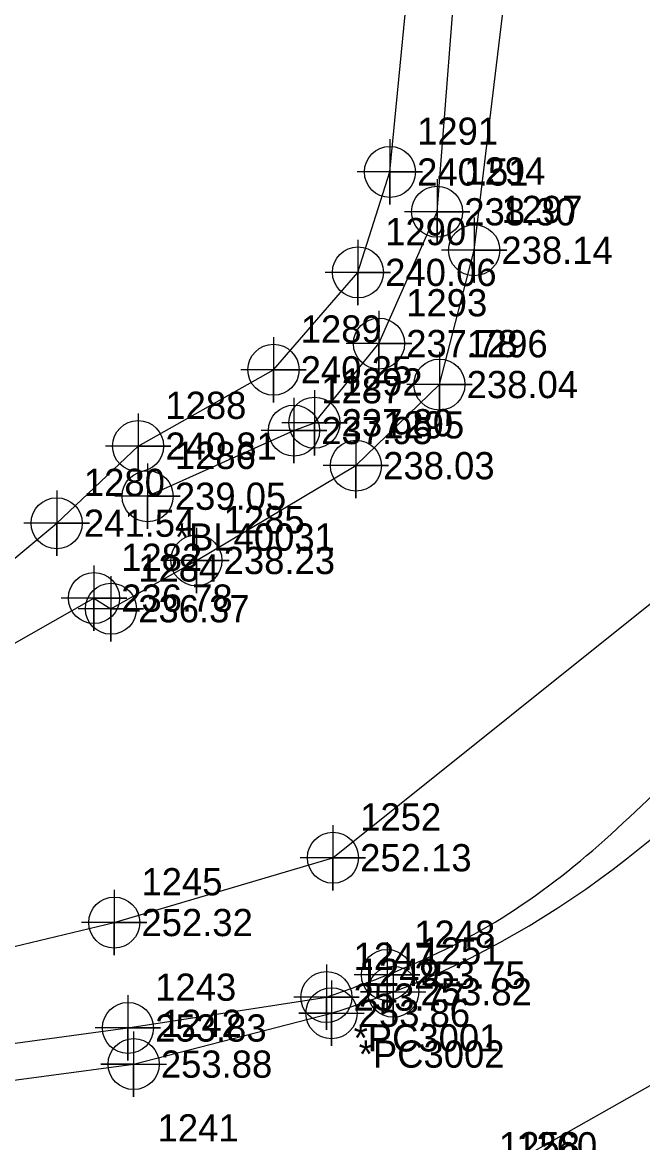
# Model space of a CAD drawing. Extents: x 2130962 to 2131465, y 643052 to 644206.
# Drawn here: x 2131138.3 to 2131195.3, y 643203.3 to 643306.2 of the extents above; entities that cross this region are included whole.
import ezdxf

# ---------------------------------------------------------------- set-up
doc = ezdxf.new("R2010")
doc.units = 0
for name, color, linetype in [('Exist DTM Breakline', 7, 'Continuous'), ('Exist DTM Breakline Cogo Elevation', 7, 'Continuous'), ('Exist DTM Breakline Cogo Number', 7, 'Continuous'), ('Exist DTM Breakline Cogo Point CELL', 7, 'Continuous'), ('Exist DTM Drainline', 7, 'Continuous'), ('Exist DTM Drainline Cogo Comment', 7, 'Continuous'), ('Exist DTM Drainline Cogo Elevation', 7, 'Continuous'), ('Exist DTM Drainline Cogo Number', 7, 'Continuous'), ('Exist DTM Drainline Cogo Point CELL', 7, 'Continuous'), ('Exist Roads EOP', 7, 'Continuous'), ('Exist Roads EOP Cogo Comment', 7, 'Continuous'), ('Exist Roads EOP Cogo Elevation', 7, 'Continuous'), ('Exist Roads EOP Cogo Number', 7, 'Continuous'), ('Exist Roads EOP Cogo Point CELL', 7, 'Continuous'), ('Exist Roads EOT', 7, 'Continuous'), ('Exist Roads EOT Cogo Comment', 7, 'Continuous'), ('Exist Roads EOT Cogo Elevation', 7, 'Continuous'), ('Exist Roads EOT Cogo Number', 7, 'Continuous'), ('Exist Roads EOT Cogo Point CELL', 7, 'Continuous')]:
    doc.layers.add(name, color=color, linetype=linetype)

msp = doc.modelspace()

# ---------------------------------------------------------------- linework, layer by layer
at = {"layer": 'Exist DTM Breakline'}
for points in [[(2131000.7408, 643235.0731), (2131050.2503, 643235.0771), (2131099.3971, 643233.3967), (2131102.4734, 643233.467), (2131117.9784, 643240.6457), (2131141.4902, 643260.2289), (2131148.9668, 643267.309), (2131161.3925, 643274.3195), (2131169.1458, 643283.2692), (2131172.0772, 643292.493), (2131174.434, 643316.7319), (2131174.0607, 643347.0813), (2131174.2633, 643367.3367), (2131180.4607, 643413.966), (2131183.0424, 643464.7744), (2131179.7562, 643510.5479), (2131157.5016, 643561.2065), (2131139.0887, 643604.6918), (2131124.996, 643650.6897)], [(2131000.2707, 643222.2884), (2131049.3172, 643219.2511), (2131099.5024, 643216.1866), (2131123.0232, 643217.8518), (2131146.7721, 643223.5416), (2131166.8509, 643229.4959), (2131199.4918, 643255.6512), (2131208.4065, 643272.9132), (2131217.3052, 643317.6851), (2131214.0619, 643367.4973), (2131211.0353, 643416.1836)]]:
    msp.add_lwpolyline(points, dxfattribs=at)
at = {"layer": 'Exist DTM Breakline Cogo Point CELL'}
for points in [[(2131172.0772, 643295.493), (2131172.0772, 643289.493), (2131172.0772, 643292.493), (2131175.0772, 643292.493), (2131169.0772, 643292.493)], [(2131169.1458, 643286.2692), (2131169.1458, 643280.2692), (2131169.1458, 643283.2692), (2131172.1458, 643283.2692), (2131166.1458, 643283.2692)], [(2131161.3925, 643277.3195), (2131161.3925, 643271.3195), (2131161.3925, 643274.3195), (2131164.3925, 643274.3195), (2131158.3925, 643274.3195)], [(2131148.9668, 643270.309), (2131148.9668, 643264.309), (2131148.9668, 643267.309), (2131151.9668, 643267.309), (2131145.9668, 643267.309)], [(2131141.4902, 643263.2289), (2131141.4902, 643257.2289), (2131141.4902, 643260.2289), (2131144.4902, 643260.2289), (2131138.4902, 643260.2289)], [(2131166.8509, 643232.4959), (2131166.8509, 643226.4959), (2131166.8509, 643229.4959), (2131169.8509, 643229.4959), (2131163.8509, 643229.4959)], [(2131146.7721, 643226.5416), (2131146.7721, 643220.5416), (2131146.7721, 643223.5416), (2131149.7721, 643223.5416), (2131143.7721, 643223.5416)]]:
    msp.add_lwpolyline(points, dxfattribs=at)
for centre in [(2131172.0772, 643292.493), (2131169.1458, 643283.2692), (2131161.3925, 643274.3195), (2131148.9668, 643267.309), (2131141.4902, 643260.2289), (2131166.8509, 643229.4959), (2131146.7721, 643223.5416)]:
    msp.add_circle(centre, 2.344, dxfattribs=at)
at = {"layer": 'Exist DTM Drainline'}
for points in [[(2131000.2029, 643226.7228), (2131050.9884, 643228.9032), (2131099.0297, 643228.5605), (2131120.2968, 643239.3591), (2131144.9156, 643253.3469), (2131146.4739, 643252.3674), (2131154.3188, 643256.8046), (2131168.9618, 643265.5132), (2131176.6257, 643272.964), (2131179.8144, 643285.303), (2131183.3842, 643315.022), (2131190.1471, 643365.8731), (2131190.1489, 643413.686), (2131192.3886, 643466.4632), (2131188.8083, 643512.615), (2131184.0059, 643563.7066), (2131175.3, 643610.7482), (2131168.3784, 643658.7431), (2131156.7476, 643707.4708), (2131144.9036, 643754.0458), (2131132.9438, 643802.544), (2131118.0831, 643847.9475), (2131104.0084, 643896.8663), (2131096.3866, 643919.4077)], [(2131149.8388, 643262.7067), (2131163.2746, 643268.7404), (2131165.1512, 643269.4553), (2131171.0778, 643276.7299), (2131176.4073, 643288.8357), (2131178.5355, 643315.9841), (2131178.9558, 643366.5567), (2131185.1892, 643414.0962), (2131192.3516, 643466.0067)]]:
    msp.add_lwpolyline(points, dxfattribs=at)
at = {"layer": 'Exist DTM Drainline Cogo Point CELL'}
for points in [[(2131176.4073, 643291.8357), (2131176.4073, 643285.8357), (2131176.4073, 643288.8357), (2131179.4073, 643288.8357), (2131173.4073, 643288.8357)], [(2131179.8144, 643288.303), (2131179.8144, 643282.303), (2131179.8144, 643285.303), (2131182.8144, 643285.303), (2131176.8144, 643285.303)], [(2131171.0778, 643279.7299), (2131171.0778, 643273.7299), (2131171.0778, 643276.7299), (2131174.0778, 643276.7299), (2131168.0778, 643276.7299)], [(2131176.6257, 643275.964), (2131176.6257, 643269.964), (2131176.6257, 643272.964), (2131179.6257, 643272.964), (2131173.6257, 643272.964)], [(2131165.1512, 643272.4553), (2131165.1512, 643266.4553), (2131165.1512, 643269.4553), (2131168.1512, 643269.4553), (2131162.1512, 643269.4553)], [(2131163.2746, 643271.7404), (2131163.2746, 643265.7404), (2131163.2746, 643268.7404), (2131166.2746, 643268.7404), (2131160.2746, 643268.7404)], [(2131168.9618, 643268.5132), (2131168.9618, 643262.5132), (2131168.9618, 643265.5132), (2131171.9618, 643265.5132), (2131165.9618, 643265.5132)], [(2131149.8388, 643265.7067), (2131149.8388, 643259.7067), (2131149.8388, 643262.7067), (2131152.8388, 643262.7067), (2131146.8388, 643262.7067)], [(2131154.3188, 643259.8046), (2131154.3188, 643253.8046), (2131154.3188, 643256.8046), (2131157.3188, 643256.8046), (2131151.3188, 643256.8046)], [(2131144.9156, 643256.3469), (2131144.9156, 643250.3469), (2131144.9156, 643253.3469), (2131147.9156, 643253.3469), (2131141.9156, 643253.3469)], [(2131146.4739, 643255.3674), (2131146.4739, 643249.3674), (2131146.4739, 643252.3674), (2131149.4739, 643252.3674), (2131143.4739, 643252.3674)]]:
    msp.add_lwpolyline(points, dxfattribs=at)
for centre in [(2131176.4073, 643288.8357), (2131179.8144, 643285.303), (2131171.0778, 643276.7299), (2131176.6257, 643272.964), (2131165.1512, 643269.4553), (2131163.2746, 643268.7404), (2131168.9618, 643265.5132), (2131149.8388, 643262.7067), (2131154.3188, 643256.8046), (2131144.9156, 643253.3469), (2131146.4739, 643252.3674)]:
    msp.add_circle(centre, 2.344, dxfattribs=at)
at = {"layer": 'Exist Roads EOP'}
msp.add_lwpolyline([(2131123.476, 643210.5181), (2131148.0359, 643213.8558), (2131166.2495, 643216.6951)], dxfattribs=at)
msp.add_spline([(2131166.2495, 643216.6951), (2131171.8131, 643218.7244), (2131182.3713, 643223.9726), (2131191.8117, 643231.1489), (2131200.5013, 643239.6993), (2131208.8071, 643249.0697), (2131216.0672, 643259.0032), (2131218.7188, 643264.347), (2131220.5363, 643270.0958), (2131222.8445, 643282.0077), (2131224.3583, 643293.9245), (2131224.8763, 643317.7904), (2131222.0632, 643367.6716), (2131218.5448, 643416.8114), (2131214.3187, 643466.3462), (2131209.1735, 643515.6666), (2131202.7939, 643565.1545), (2131195.0475, 643613.9937), (2131186.4014, 643662.4763), (2131176.0113, 643711.405), (2131164.6154, 643759.8896), (2131151.874, 643807.8526), (2131137.8554, 643855.4065), (2131122.5733, 643902.8574), (2131105.9622, 643949.4862), (2131091.5349, 643988.0437)], degree=3, dxfattribs=at)
at = {"layer": 'Exist Roads EOP Cogo Point CELL'}
for points in [[(2131171.8131, 643221.7244), (2131171.8131, 643215.7244), (2131171.8131, 643218.7244), (2131174.8131, 643218.7244), (2131168.8131, 643218.7244)], [(2131166.2495, 643219.6951), (2131166.2495, 643213.6951), (2131166.2495, 643216.6951), (2131169.2495, 643216.6951), (2131163.2495, 643216.6951)], [(2131148.0359, 643216.8558), (2131148.0359, 643210.8558), (2131148.0359, 643213.8558), (2131151.0359, 643213.8558), (2131145.0359, 643213.8558)]]:
    msp.add_lwpolyline(points, dxfattribs=at)
for centre in [(2131171.8131, 643218.7244), (2131166.2495, 643216.6951), (2131148.0359, 643213.8558)]:
    msp.add_circle(centre, 2.344, dxfattribs=at)
at = {"layer": 'Exist Roads EOT'}
for points in [[(2131123.8135, 643207.212), (2131148.5569, 643210.5345), (2131166.718, 643215.2083)], [(2131179.5807, 643199.2911), (2131205.8187, 643214.1331)]]:
    msp.add_lwpolyline(points, dxfattribs=at)
msp.add_spline([(2131166.718, 643215.2083), (2131172.3866, 643217.1804), (2131211.4056, 643247.1499), (2131223.758, 643268.7314), (2131228.3848, 643317.935), (2131225.533, 643367.8628), (2131222.2486, 643417.1873), (2131217.9619, 643466.6275), (2131212.8794, 643516.2377), (2131206.5633, 643565.5764), (2131198.9021, 643614.6757), (2131189.6851, 643663.4055), (2131179.3985, 643712.1311), (2131168.3085, 643760.7185), (2131155.755, 643808.9129), (2131141.6748, 643856.5528), (2131126.5354, 643904.2758), (2131110.3559, 643951.0191), (2131092.4533, 643998.1348), (2131073.722, 644043.631), (2131053.1654, 644089.359), (2131032.0052, 644134.0908), (2131009.0644, 644179.3802)], degree=3, dxfattribs=at)
at = {"layer": 'Exist Roads EOT Cogo Point CELL'}
for points in [[(2131172.3866, 643220.1804), (2131172.3866, 643214.1804), (2131172.3866, 643217.1804), (2131169.3866, 643217.1804), (2131175.3866, 643217.1804)], [(2131166.718, 643218.2083), (2131166.718, 643212.2083), (2131166.718, 643215.2083), (2131163.718, 643215.2083), (2131169.718, 643215.2083)], [(2131148.5569, 643213.5345), (2131148.5569, 643207.5345), (2131148.5569, 643210.5345), (2131145.5569, 643210.5345), (2131151.5569, 643210.5345)]]:
    msp.add_lwpolyline(points, dxfattribs=at)
for centre in [(2131172.3866, 643217.1804), (2131166.718, 643215.2083), (2131148.5569, 643210.5345)]:
    msp.add_circle(centre, 2.344, dxfattribs=at)

# ---------------------------------------------------------------- texts
at = {"layer": 'Exist DTM Breakline Cogo Elevation'}
for s, p in [('240.51', (2131174.5772, 643291.243)), ('240.06', (2131171.6458, 643282.0192)), ('240.25', (2131163.8925, 643273.0695)), ('240.81', (2131151.4668, 643266.059)), ('241.54', (2131143.9902, 643258.9789)), ('252.13', (2131169.3509, 643228.2459)), ('252.32', (2131149.2721, 643222.2916))]:
    msp.add_text(s, height=2.5, dxfattribs=at).set_placement(p)
at = {"layer": 'Exist DTM Breakline Cogo Number'}
for s, p in [('1291', (2131174.5772, 643294.993)), ('1290', (2131171.6458, 643285.7692)), ('1289', (2131163.8925, 643276.8195)), ('1288', (2131151.4668, 643269.809)), ('1280', (2131143.9902, 643262.7289)), ('1252', (2131169.3509, 643231.9959)), ('1245', (2131149.2721, 643226.0416))]:
    msp.add_text(s, height=2.5, dxfattribs=at).set_placement(p)
at = {"layer": 'Exist DTM Drainline Cogo Comment'}
msp.add_text('*BL40031', height=2.5, dxfattribs=at).set_placement((2131152.3388, 643257.7067))
at = {"layer": 'Exist DTM Drainline Cogo Elevation'}
for s, p in [('238.30', (2131178.9073, 643287.5857)), ('238.14', (2131182.3144, 643284.053)), ('237.78', (2131173.5778, 643275.4799)), ('238.04', (2131179.1257, 643271.714)), ('237.80', (2131167.6512, 643268.2053)), ('237.95', (2131165.7746, 643267.4904)), ('238.03', (2131171.4618, 643264.2632)), ('239.05', (2131152.3388, 643261.4567)), ('238.23', (2131156.8188, 643255.5546)), ('236.78', (2131147.4156, 643252.0969)), ('236.37', (2131148.9739, 643251.1174))]:
    msp.add_text(s, height=2.5, dxfattribs=at).set_placement(p)
at = {"layer": 'Exist DTM Drainline Cogo Number'}
for s, p in [('1294', (2131178.9073, 643291.3357)), ('1297', (2131182.3144, 643287.803)), ('1293', (2131173.5778, 643279.2299)), ('1296', (2131179.1257, 643275.464)), ('1292', (2131167.6512, 643271.9553)), ('1287', (2131165.7746, 643271.2404)), ('1295', (2131171.4618, 643268.0132)), ('1286', (2131152.3388, 643265.2067)), ('1285', (2131156.8188, 643259.3046)), ('1282', (2131147.4156, 643255.8469)), ('1284', (2131148.9739, 643254.8674))]:
    msp.add_text(s, height=2.5, dxfattribs=at).set_placement(p)
at = {"layer": 'Exist Roads EOP Cogo Comment'}
msp.add_text('*PC3001', height=2.5, dxfattribs=at).set_placement((2131168.7495, 643211.6951))
at = {"layer": 'Exist Roads EOP Cogo Elevation'}
for s, p in [('253.75', (2131174.3131, 643217.4744)), ('253.77', (2131168.7495, 643215.4451)), ('253.83', (2131150.5359, 643212.6058))]:
    msp.add_text(s, height=2.5, dxfattribs=at).set_placement(p)
at = {"layer": 'Exist Roads EOP Cogo Number'}
for s, p in [('1248', (2131174.3131, 643221.2244)), ('1247', (2131168.7495, 643219.1951)), ('1243', (2131150.5359, 643216.3558))]:
    msp.add_text(s, height=2.5, dxfattribs=at).set_placement(p)
at = {"layer": 'Exist Roads EOT Cogo Comment'}
msp.add_text('*PC3002', height=2.5, dxfattribs=at).set_placement((2131169.218, 643210.2083))
at = {"layer": 'Exist Roads EOT Cogo Elevation'}
for s, p in [('253.82', (2131174.8866, 643215.9304)), ('253.86', (2131169.218, 643213.9583)), ('253.88', (2131151.0569, 643209.2845))]:
    msp.add_text(s, height=2.5, dxfattribs=at).set_placement(p)
at = {"layer": 'Exist Roads EOT Cogo Number'}
for s, p in [('1251', (2131174.8866, 643219.6804)), ('1249', (2131169.218, 643217.7083)), ('1242', (2131151.0569, 643213.0345)), ('1241', (2131150.7562, 643203.4286)), ('1258', (2131182.0807, 643201.7911)), ('1260', (2131183.6737, 643201.7827))]:
    msp.add_text(s, height=2.5, dxfattribs=at).set_placement(p)

doc.saveas('drawing.dxf')
